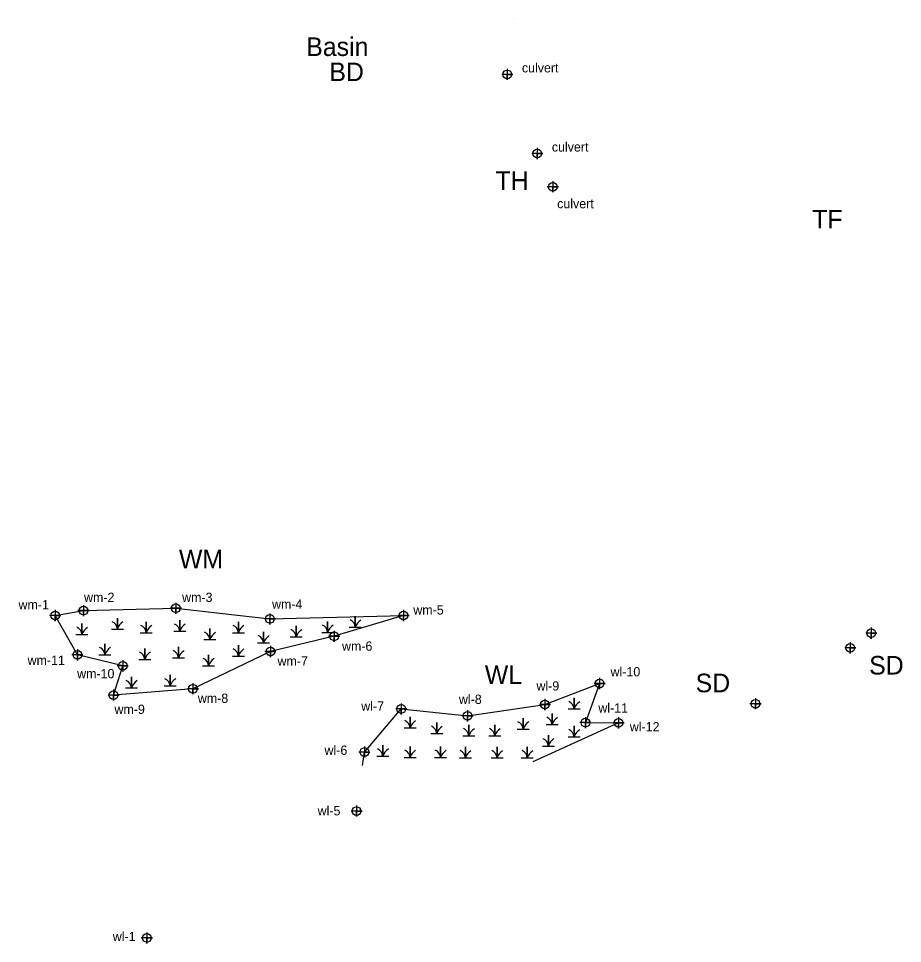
# Model space of a CAD drawing. Extents: x 2174810 to 2196950, y 76168 to 88270.
# Drawn here: x 2192998.2 to 2193473.9, y 86408.6 to 86906.3 of the extents above; entities that cross this region are included whole.
import ezdxf

# ---------------------------------------------------------------- set-up
doc = ezdxf.new("R2010")
doc.units = 0
for name, color, linetype in [('Exist Environmental Wetland Boundary', 7, 'Continuous'), ('Exist Environmental Wetland Boundary Cogo Point CELL', 7, 'Continuous'), ('Exist Environmental Wetland Boundary Text', 7, 'Continuous'), ('Exist Hydro Jurisdictional Stream or Body of Water Mitigable', 7, 'Continuous'), ('Exist Hydro Jurisdictional Stream or Body of Water Mitigable Cogo Number', 7, 'Continuous'), ('Exist Hydro Jurisdictional Stream or Body of Water Mitigable Cogo Point CELL', 7, 'Continuous'), ('Exist Hydro Jurisdictional Stream or Body of Water NonMitigable', 7, 'Continuous'), ('Exist Hydro Jurisdictional Stream or Body of Water NonMitigable Cogo Number', 7, 'Continuous'), ('Exist Hydro Jurisdictional Stream or Body of Water NonMitigable Cogo Point CELL', 7, 'Continuous'), ('Exist Hydro Jurisdictional Stream or Body of Water NonMitigable Text', 7, 'Continuous'), ('Exist Hydro Swamp or Marsh', 7, 'Continuous')]:
    doc.layers.add(name, color=color, linetype=linetype)

msp = doc.modelspace()

# ---------------------------------------------------------------- linework, layer by layer
at = {"layer": 'Exist Environmental Wetland Boundary'}
msp.add_lwpolyline([(2193018, 86585.13), (2193033.21, 86587.73), (2193082.92, 86588.97), (2193133.54, 86583.25), (2193205.43, 86585.1), (2193168.07, 86573.89), (2193133.77, 86565.71), (2193092.12, 86545.69), (2193049.41, 86542.27), (2193054.3, 86557.98), (2193029.93, 86563.91)], close=True, dxfattribs=at)
msp.add_lwpolyline([(2193183.38, 86504.32), (2193184.34, 86511.64), (2193204.19, 86534.79), (2193239.87, 86531.11), (2193281.47, 86537.2), (2193310.91, 86548.52), (2193303.25, 86527.44), (2193321.1, 86527.38), (2193275.05, 86506.37)], dxfattribs=at)
at = {"layer": 'Exist Environmental Wetland Boundary Cogo Point CELL'}
for points in [[(2193033.21, 86590.73), (2193033.21, 86584.73), (2193033.21, 86587.73), (2193036.21, 86587.73), (2193030.21, 86587.73)], [(2193082.92, 86591.97), (2193082.92, 86585.97), (2193082.92, 86588.97), (2193085.92, 86588.97), (2193079.92, 86588.97)], [(2193018, 86588.13), (2193018, 86582.13), (2193018, 86585.13), (2193021, 86585.13), (2193015, 86585.13)], [(2193133.54, 86586.25), (2193133.54, 86580.25), (2193133.54, 86583.25), (2193136.54, 86583.25), (2193130.54, 86583.25)], [(2193205.43, 86588.1), (2193205.43, 86582.1), (2193205.43, 86585.1), (2193208.43, 86585.1), (2193202.43, 86585.1)], [(2193168.07, 86576.89), (2193168.07, 86570.89), (2193168.07, 86573.89), (2193171.07, 86573.89), (2193165.07, 86573.89)], [(2193029.93, 86566.91), (2193029.93, 86560.91), (2193029.93, 86563.91), (2193032.93, 86563.91), (2193026.93, 86563.91)], [(2193133.77, 86568.71), (2193133.77, 86562.71), (2193133.77, 86565.71), (2193136.77, 86565.71), (2193130.77, 86565.71)], [(2193054.3, 86560.98), (2193054.3, 86554.98), (2193054.3, 86557.98), (2193057.3, 86557.98), (2193051.3, 86557.98)], [(2193310.91, 86551.52), (2193310.91, 86545.52), (2193310.91, 86548.52), (2193313.91, 86548.52), (2193307.91, 86548.52)], [(2193049.41, 86545.27), (2193049.41, 86539.27), (2193049.41, 86542.27), (2193052.41, 86542.27), (2193046.41, 86542.27)], [(2193092.12, 86548.69), (2193092.12, 86542.69), (2193092.12, 86545.69), (2193095.12, 86545.69), (2193089.12, 86545.69)], [(2193281.47, 86540.2), (2193281.47, 86534.2), (2193281.47, 86537.2), (2193284.47, 86537.2), (2193278.47, 86537.2)], [(2193204.19, 86537.79), (2193204.19, 86531.79), (2193204.19, 86534.79), (2193207.19, 86534.79), (2193201.19, 86534.79)], [(2193239.87, 86534.11), (2193239.87, 86528.11), (2193239.87, 86531.11), (2193242.87, 86531.11), (2193236.87, 86531.11)], [(2193303.25, 86530.44), (2193303.25, 86524.44), (2193303.25, 86527.44), (2193306.25, 86527.44), (2193300.25, 86527.44)], [(2193321.1, 86530.38), (2193321.1, 86524.38), (2193321.1, 86527.38), (2193324.1, 86527.38), (2193318.1, 86527.38)], [(2193184.34, 86514.64), (2193184.34, 86508.64), (2193184.34, 86511.64), (2193187.34, 86511.64), (2193181.34, 86511.64)], [(2193180.14, 86482.88), (2193180.14, 86476.88), (2193180.14, 86479.88), (2193183.14, 86479.88), (2193177.14, 86479.88)], [(2193067.33, 86414.6), (2193067.33, 86408.6), (2193067.33, 86411.6), (2193070.33, 86411.6), (2193064.33, 86411.6)]]:
    msp.add_lwpolyline(points, dxfattribs=at)
for centre in [(2193033.21, 86587.73), (2193082.92, 86588.97), (2193018, 86585.13), (2193133.54, 86583.25), (2193205.43, 86585.1), (2193168.07, 86573.89), (2193029.93, 86563.91), (2193133.77, 86565.71), (2193054.3, 86557.98), (2193310.91, 86548.52), (2193049.41, 86542.27), (2193092.12, 86545.69), (2193204.19, 86534.79), (2193281.47, 86537.2), (2193239.87, 86531.11), (2193303.25, 86527.44), (2193321.1, 86527.38), (2193184.34, 86511.64), (2193180.14, 86479.88), (2193067.33, 86411.6)]:
    msp.add_circle(centre, 2.34, dxfattribs=at)
at = {"layer": 'Exist Hydro Jurisdictional Stream or Body of Water Mitigable Cogo Point CELL'}
for points in [[(2193457.07, 86578.58), (2193457.07, 86572.58), (2193457.07, 86575.58), (2193460.07, 86575.58), (2193454.07, 86575.58)], [(2193445.77, 86570.66), (2193445.77, 86564.66), (2193445.77, 86567.66), (2193448.77, 86567.66), (2193442.77, 86567.66)], [(2193394.76, 86540.63), (2193394.76, 86534.63), (2193394.76, 86537.63), (2193397.76, 86537.63), (2193391.76, 86537.63)]]:
    msp.add_lwpolyline(points, dxfattribs=at)
for centre in [(2193457.07, 86575.58), (2193445.77, 86567.66), (2193394.76, 86537.63)]:
    msp.add_circle(centre, 2.34, dxfattribs=at)
at = {"layer": 'Exist Hydro Jurisdictional Stream or Body of Water NonMitigable'}
msp.add_line((2193265.25, 86906.33), (2193265.25, 86906.33), dxfattribs=at)
at = {"layer": 'Exist Hydro Jurisdictional Stream or Body of Water NonMitigable Cogo Point CELL'}
for points in [[(2193261.23, 86879.26), (2193261.23, 86873.26), (2193261.23, 86876.26), (2193264.23, 86876.26), (2193258.23, 86876.26)], [(2193277.35, 86836.66), (2193277.35, 86830.66), (2193277.35, 86833.66), (2193280.35, 86833.66), (2193274.35, 86833.66)], [(2193285.72, 86818.8), (2193285.72, 86812.8), (2193285.72, 86815.8), (2193288.72, 86815.8), (2193282.72, 86815.8)]]:
    msp.add_lwpolyline(points, dxfattribs=at)
for centre in [(2193261.23, 86876.26), (2193277.35, 86833.66), (2193285.72, 86815.8)]:
    msp.add_circle(centre, 2.34, dxfattribs=at)
at = {"layer": 'Exist Hydro Swamp or Marsh'}
for points in [[(2193176.23, 86578.81), (2193179.46, 86578.81), (2193179.46, 86584.73), (2193179.46, 86578.81), (2193182.68, 86578.81)], [(2193029.17, 86574.86), (2193032.4, 86574.86), (2193032.4, 86580.78), (2193032.4, 86574.86), (2193035.62, 86574.86)], [(2193048.22, 86577.83), (2193051.45, 86577.83), (2193051.45, 86583.75), (2193051.45, 86577.83), (2193054.68, 86577.83)], [(2193063.72, 86575.84), (2193066.95, 86575.84), (2193066.95, 86581.75), (2193066.95, 86575.84), (2193070.17, 86575.84)], [(2193081.76, 86576.59), (2193084.98, 86576.59), (2193084.98, 86582.5), (2193084.98, 86576.59), (2193088.21, 86576.59)], [(2193113.31, 86575.85), (2193116.54, 86575.85), (2193116.54, 86581.77), (2193116.54, 86575.85), (2193119.76, 86575.85)], [(2193144.4, 86573.63), (2193147.63, 86573.63), (2193147.63, 86579.54), (2193147.63, 86573.63), (2193150.85, 86573.63)], [(2193161.36, 86576.01), (2193164.58, 86576.01), (2193164.58, 86581.93), (2193164.58, 86576.01), (2193167.81, 86576.01)], [(2193098.01, 86572.14), (2193101.24, 86572.14), (2193101.24, 86578.06), (2193101.24, 86572.14), (2193104.46, 86572.14)], [(2193126.88, 86570.42), (2193130.11, 86570.42), (2193130.11, 86576.33), (2193130.11, 86570.42), (2193133.33, 86570.42)], [(2193041.51, 86564), (2193044.73, 86564), (2193044.73, 86569.91), (2193044.73, 86564), (2193047.96, 86564)], [(2193062.97, 86561.5), (2193066.2, 86561.5), (2193066.2, 86567.42), (2193066.2, 86561.5), (2193069.42, 86561.5)], [(2193081.06, 86562.31), (2193084.29, 86562.31), (2193084.29, 86568.23), (2193084.29, 86562.31), (2193087.52, 86562.31)], [(2193113.31, 86563.26), (2193116.54, 86563.26), (2193116.54, 86569.17), (2193116.54, 86563.26), (2193119.76, 86563.26)], [(2193097.27, 86558.07), (2193100.5, 86558.07), (2193100.5, 86563.99), (2193100.5, 86558.07), (2193103.72, 86558.07)], [(2193055.82, 86546.22), (2193059.04, 86546.22), (2193059.04, 86552.14), (2193059.04, 86546.22), (2193062.27, 86546.22)], [(2193076.61, 86547.17), (2193079.84, 86547.17), (2193079.84, 86553.09), (2193079.84, 86547.17), (2193083.06, 86547.17)], [(2193293.93, 86534.86), (2193297.15, 86534.86), (2193297.15, 86540.78), (2193297.15, 86534.86), (2193300.38, 86534.86)], [(2193205.66, 86524.66), (2193208.89, 86524.66), (2193208.89, 86530.58), (2193208.89, 86524.66), (2193212.12, 86524.66)], [(2193266.54, 86524), (2193269.77, 86524), (2193269.77, 86529.92), (2193269.77, 86524), (2193272.99, 86524)], [(2193282.08, 86526.47), (2193285.31, 86526.47), (2193285.31, 86532.39), (2193285.31, 86526.47), (2193288.54, 86526.47)], [(2193220.04, 86521.55), (2193223.26, 86521.55), (2193223.26, 86527.47), (2193223.26, 86521.55), (2193226.49, 86521.55)], [(2193237.28, 86520.29), (2193240.5, 86520.29), (2193240.5, 86526.21), (2193240.5, 86520.29), (2193243.73, 86520.29)], [(2193251.24, 86520.29), (2193254.47, 86520.29), (2193254.47, 86526.21), (2193254.47, 86520.29), (2193257.69, 86520.29)], [(2193293.93, 86519.8), (2193297.15, 86519.8), (2193297.15, 86525.72), (2193297.15, 86519.8), (2193300.38, 86519.8)], [(2193280.11, 86514.86), (2193283.34, 86514.86), (2193283.34, 86520.78), (2193283.34, 86514.86), (2193286.56, 86514.86)], [(2193191.04, 86509.43), (2193194.26, 86509.43), (2193194.26, 86515.35), (2193194.26, 86509.43), (2193197.49, 86509.43)], [(2193205.66, 86508.75), (2193208.89, 86508.75), (2193208.89, 86514.66), (2193208.89, 86508.75), (2193212.12, 86508.75)], [(2193222.12, 86508.75), (2193225.34, 86508.75), (2193225.34, 86514.66), (2193225.34, 86508.75), (2193228.57, 86508.75)], [(2193235.45, 86508.44), (2193238.68, 86508.44), (2193238.68, 86514.36), (2193238.68, 86508.44), (2193241.9, 86508.44)], [(2193252.48, 86508.44), (2193255.7, 86508.44), (2193255.7, 86514.36), (2193255.7, 86508.44), (2193258.93, 86508.44)], [(2193268.76, 86508.44), (2193271.99, 86508.44), (2193271.99, 86514.36), (2193271.99, 86508.44), (2193275.21, 86508.44)]]:
    msp.add_lwpolyline(points, dxfattribs=at)
for centre, radius, start, end in [((2193046.85, 86577.5), 4.61, 4.1403, 67.535), ((2193058.29, 86575.56), 7.21, 122.1274, 161.6222), ((2193062.35, 86575.5), 4.61, 4.1403, 67.535), ((2193073.79, 86573.56), 7.21, 122.1274, 161.6222), ((2193080.38, 86576.25), 4.61, 4.1403, 67.535), ((2193091.82, 86574.31), 7.21, 122.1274, 161.6222), ((2193111.94, 86575.52), 4.61, 4.1403, 67.535), ((2193123.38, 86573.58), 7.21, 122.1274, 161.6222), ((2193159.98, 86575.68), 4.61, 4.1403, 67.535), ((2193171.42, 86573.74), 7.21, 122.1274, 161.6222), ((2193174.86, 86578.48), 4.61, 4.1403, 67.535), ((2193186.3, 86576.54), 7.21, 122.1274, 161.6222), ((2193027.8, 86574.53), 4.61, 4.1403, 67.535), ((2193039.24, 86572.59), 7.21, 122.1274, 161.6222), ((2193096.64, 86571.81), 4.61, 4.1403, 67.535), ((2193108.08, 86569.87), 7.21, 122.1274, 161.6222), ((2193143.03, 86573.29), 4.61, 4.1403, 67.535), ((2193154.47, 86571.35), 7.21, 122.1274, 161.6222), ((2193125.51, 86570.08), 4.61, 4.1403, 67.535), ((2193136.95, 86568.14), 7.21, 122.1274, 161.6222), ((2193040.13, 86563.66), 4.61, 4.1403, 67.535), ((2193051.57, 86561.72), 7.21, 122.1274, 161.6222), ((2193061.6, 86561.17), 4.61, 4.1403, 67.535), ((2193073.04, 86559.23), 7.21, 122.1274, 161.6222), ((2193079.69, 86561.98), 4.61, 4.1403, 67.535), ((2193091.13, 86560.04), 7.21, 122.1274, 161.6222), ((2193111.94, 86562.92), 4.61, 4.1403, 67.535), ((2193123.38, 86560.98), 7.21, 122.1274, 161.6222), ((2193095.9, 86557.74), 4.61, 4.1403, 67.535), ((2193107.34, 86555.8), 7.21, 122.1274, 161.6222), ((2193054.44, 86545.89), 4.61, 4.1403, 67.535), ((2193065.89, 86543.95), 7.21, 122.1274, 161.6222), ((2193075.24, 86546.83), 4.61, 4.1403, 67.535), ((2193086.68, 86544.89), 7.21, 122.1274, 161.6222), ((2193292.55, 86534.53), 4.61, 4.1403, 67.535), ((2193304, 86532.59), 7.21, 122.1274, 161.6222), ((2193280.71, 86526.13), 4.61, 4.1403, 67.535), ((2193292.15, 86524.19), 7.21, 122.1274, 161.6222), ((2193204.29, 86524.33), 4.61, 4.1403, 67.535), ((2193215.73, 86522.39), 7.21, 122.1274, 161.6222), ((2193218.66, 86521.21), 4.61, 4.1403, 67.535), ((2193230.1, 86519.27), 7.21, 122.1274, 161.6222), ((2193265.17, 86523.67), 4.61, 4.1403, 67.535), ((2193276.61, 86521.73), 7.21, 122.1274, 161.6222), ((2193235.9, 86519.96), 4.61, 4.1403, 67.535), ((2193247.34, 86518.02), 7.21, 122.1274, 161.6222), ((2193249.87, 86519.96), 4.61, 4.1403, 67.535), ((2193261.31, 86518.02), 7.21, 122.1274, 161.6222), ((2193292.55, 86519.47), 4.61, 4.1403, 67.535), ((2193304, 86517.53), 7.21, 122.1274, 161.6222), ((2193278.74, 86514.53), 4.61, 4.1403, 67.535), ((2193290.18, 86512.59), 7.21, 122.1274, 161.6222), ((2193189.66, 86509.1), 4.61, 4.1403, 67.535), ((2193201.1, 86507.16), 7.21, 122.1274, 161.6222), ((2193204.29, 86508.41), 4.61, 4.1403, 67.535), ((2193215.73, 86506.47), 7.21, 122.1274, 161.6222), ((2193220.74, 86508.41), 4.61, 4.1403, 67.535), ((2193232.18, 86506.47), 7.21, 122.1274, 161.6222), ((2193234.08, 86508.11), 4.61, 4.1403, 67.535), ((2193245.52, 86506.17), 7.21, 122.1274, 161.6222), ((2193251.1, 86508.11), 4.61, 4.1403, 67.535), ((2193262.54, 86506.17), 7.21, 122.1274, 161.6222), ((2193267.39, 86508.11), 4.61, 4.1403, 67.535), ((2193278.83, 86506.17), 7.21, 122.1274, 161.6222)]:
    msp.add_arc(centre, radius, start, end, dxfattribs=at)

# ---------------------------------------------------------------- texts
at = {"layer": 'Exist Environmental Wetland Boundary Text'}
for s, p in [('WM', (2193084.56, 86610.46)), ('WL', (2193249.13, 86548.27))]:
    msp.add_text(s, height=10, dxfattribs=at).set_placement(p)
at = {"layer": 'Exist Hydro Jurisdictional Stream or Body of Water Mitigable'}
for p in [(2193455.92, 86553.33), (2193362.55, 86543.8)]:
    msp.add_text('SD', height=10, dxfattribs=at).set_placement(p)
at = {"layer": 'Exist Hydro Jurisdictional Stream or Body of Water Mitigable Cogo Number'}
for s, p in [('wm-2', (2193033.51, 86592.38)), ('wm-3', (2193086.26, 86592.38)), ('wm-1', (2192998.25, 86588.43)), ('wm-4', (2193134.64, 86588.71)), ('wm-5', (2193210.66, 86585.61)), ('wm-6', (2193172.3, 86566.14)), ('wm-11', (2193003.13, 86558.52)), ('wm-7', (2193137.6, 86558.09)), ('wm-10', (2193029.79, 86551.32)), ('wl-10', (2193316.77, 86552.34)), ('wl-9', (2193276.92, 86544.69)), ('wm-8', (2193094.73, 86538.06)), ('wl-8', (2193235.2, 86537.53)), ('wm-9', (2193049.88, 86532.13)), ('wl-7', (2193182.63, 86533.83)), ('wl-11', (2193310.21, 86532.84)), ('wl-12', (2193327.14, 86522.72)), ('wl-6', (2193162.88, 86510.12)), ('wl-5', (2193159.18, 86477.53)), ('wl-1', (2193048.96, 86409.88))]:
    msp.add_text(s, height=5, dxfattribs=at).set_placement(p)
at = {"layer": 'Exist Hydro Jurisdictional Stream or Body of Water NonMitigable Cogo Number'}
for p in [(2193269.08, 86877.32), (2193285.2, 86834.73), (2193288.05, 86804.24)]:
    msp.add_text('culvert', height=5, dxfattribs=at).set_placement(p)
at = {"layer": 'Exist Hydro Jurisdictional Stream or Body of Water NonMitigable Text'}
for s, p in [('Basin', (2193153.06, 86886.16)), ('BD', (2193165.49, 86872.62)), ('TH', (2193254.86, 86814.11)), ('TF', (2193425.3, 86793.37))]:
    msp.add_text(s, height=10, dxfattribs=at).set_placement(p)

doc.saveas('drawing.dxf')
